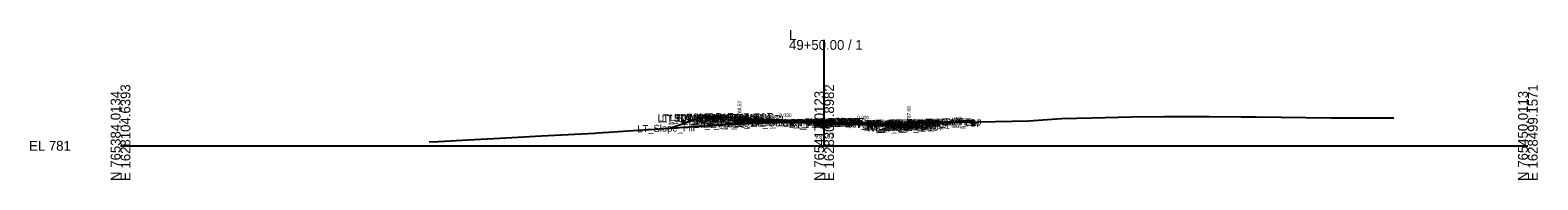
# Model space of a CAD drawing. Extents: x -26 to 4403, y -510 to 9556.
# Drawn here: x 2974.3 to 3402.8, y 9490.3 to 9532.9 of the extents above; entities that cross this region are included whole.
import ezdxf

# ---------------------------------------------------------------- set-up
doc = ezdxf.new("R2010")
doc.units = 0
for name, color, linetype in [('Default', 7, 'Continuous'), ('Exist CMT Pavement', 7, 'Continuous'), ('Exist Cross Section Cell', 7, 'Continuous'), ('Exist XS Center Line Elevation Label', 7, 'Continuous'), ('Exist XS Ground Line', 7, 'Continuous'), ('Prop CMT Conc Surface', 7, 'Continuous'), ('Prop CMT Concrete Structures', 7, 'Continuous'), ('Prop CMT Pvmt Course 1', 7, 'Continuous'), ('Prop CMT Pvmt Course 1 CG', 7, 'Continuous'), ('Prop CMT Pvmt Course 1 Wedge', 7, 'Continuous'), ('Prop CMT Pvmt Course 2', 7, 'Continuous'), ('Prop CMT Pvmt Course 2 Wedge', 7, 'Continuous'), ('Prop CMT Pvmt Course 3', 7, 'Continuous'), ('Prop CMT Pvmt Course 3 Wedge', 7, 'Continuous'), ('Prop CMT Pvmt Surface', 7, 'Continuous'), ('Prop CMT Pvmt Wedge Surface 1', 7, 'Continuous'), ('Prop CMT Pvmt Wedge Surface 2', 7, 'Continuous'), ('Prop CMT Pvmt Wedge Surface 3', 7, 'Continuous'), ('Prop CMT Slope Grass', 7, 'Continuous'), ('Prop CMT Subgrade Earthwork', 7, 'Continuous'), ('Prop XS Finish Grade CurbGutter', 7, 'Continuous'), ('Prop XS Hydro Elevations', 7, 'Continuous'), ('Prop XS SE Text', 7, 'Continuous'), ('Prop XS Side Slope Text', 7, 'Continuous'), ('Scratch_Level_0', 7, 'Continuous')]:
    doc.layers.add(name, color=color, linetype=linetype)

msp = doc.modelspace()

# ---------------------------------------------------------------- linework, layer by layer
at = {"layer": 'Exist CMT Pavement'}
for points in [[(3200, 9506.67), (3195.02, 9506.71), (3191.63, 9506.72), (3182.69, 9506.5), (3178.93, 9506.41), (3177.93, 9506.36)], [(3200, 9506.67), (3203.86, 9506.64), (3206.93, 9506.54), (3215.98, 9506.21), (3217.93, 9506.15), (3218.38, 9506.15), (3219.81, 9506.21), (3221.76, 9506.3), (3222.06, 9506.3)]]:
    msp.add_lwpolyline(points, dxfattribs=at)
at = {"layer": 'Exist Cross Section Cell'}
for p, q in [((3200, 9500), (3200, 9530.1)), ((3000, 9500), (3200, 9500)), ((3200, 9500), (3400, 9500))]:
    msp.add_line(p, q, dxfattribs=at)
at = {"layer": 'Exist XS Ground Line'}
msp.add_lwpolyline([(3087.7, 9501.12), (3090.33, 9501.26), (3098.82, 9501.68), (3107.8, 9502.14), (3119.66, 9502.81), (3132.87, 9503.52), (3134.73, 9503.62), (3135.48, 9503.64), (3138.81, 9503.86), (3149.78, 9504.63), (3150.39, 9504.64), (3174.49, 9506.2), (3175.85, 9506.27), (3176.16, 9506.28), (3178.93, 9506.41), (3182.69, 9506.5), (3191.63, 9506.72), (3195.02, 9506.71), (3200, 9506.67), (3203.86, 9506.64), (3206.93, 9506.54), (3215.98, 9506.21), (3217.93, 9506.15), (3218.38, 9506.15), (3219.81, 9506.21), (3221.76, 9506.3), (3223.51, 9506.31), (3224.89, 9506.42), (3225.44, 9506.5), (3229.86, 9506.59), (3234.45, 9506.64), (3258.2, 9507.08), (3267.44, 9507.81), (3276.18, 9507.97), (3287.38, 9508.26), (3296.52, 9508.36), (3309.39, 9508.3), (3318.51, 9508.28), (3321.3, 9508.26), (3322.77, 9508.23), (3344.04, 9507.99), (3361.94, 9507.97)], dxfattribs=at)
at = {"layer": 'Prop CMT Conc Surface'}
for points in [[(3171.42, 9508.11), (3166.42, 9508.21)], [(3175.92, 9507.52), (3175.92, 9508.02), (3175.42, 9508.02)], [(3177.93, 9507.54), (3175.92, 9507.52)], [(3222.08, 9506.22), (3224.08, 9506.08)], [(3224.08, 9506.08), (3224.08, 9506.58), (3224.58, 9506.58)], [(3228.58, 9506.67), (3233.58, 9506.77)]]:
    msp.add_lwpolyline(points, dxfattribs=at)
at = {"layer": 'Prop CMT Concrete Structures'}
for points in [[(3166.42, 9507.88), (3166.42, 9508.21)], [(3166.42, 9508.21), (3171.42, 9508.11)], [(3171.42, 9507.78), (3166.42, 9507.88)], [(3171.42, 9508.11), (3171.42, 9507.78)], [(3177.93, 9507.54), (3175.92, 9507.52), (3175.92, 9508.02), (3175.42, 9508.02)], [(3175.42, 9508.02), (3175.43, 9507.04), (3177.93, 9506.96)], [(3177.93, 9506.96), (3177.93, 9507.54)], [(3222.08, 9506.22), (3224.08, 9506.08), (3224.08, 9506.58), (3224.58, 9506.58)], [(3224.58, 9506.58), (3224.58, 9505.56), (3222.08, 9505.64)], [(3222.08, 9505.64), (3222.08, 9506.22)], [(3233.58, 9506.77), (3228.58, 9506.67)], [(3228.58, 9506.67), (3228.58, 9506.34)], [(3228.58, 9506.34), (3233.58, 9506.44)], [(3233.58, 9506.44), (3233.58, 9506.77)]]:
    msp.add_lwpolyline(points, dxfattribs=at)
at = {"layer": 'Prop CMT Pvmt Course 1'}
for points in [[(3200, 9506.88), (3177.93, 9507.54)], [(3177.93, 9507.54), (3177.93, 9507.29), (3177.93, 9507.29), (3177.93, 9507.42)], [(3177.93, 9507.42), (3200, 9506.76)], [(3200, 9506.88), (3222.08, 9506.22)], [(3200, 9506.63), (3200, 9506.88)], [(3200, 9506.63), (3200, 9506.88)], [(3222.08, 9506.09), (3200, 9506.76)], [(3200, 9506.76), (3200, 9506.63), (3200, 9506.63)], [(3200, 9506.76), (3200, 9506.63), (3200, 9506.63)], [(3222.08, 9506.22), (3222.08, 9505.97), (3222.08, 9505.97), (3222.08, 9506.09)]]:
    msp.add_lwpolyline(points, dxfattribs=at)
at = {"layer": 'Prop CMT Pvmt Course 1 CG'}
for points in [[(3177.93, 9506.96), (3174.93, 9507.05), (3174.6, 9506.73)], [(3174.6, 9506.73), (3177.93, 9506.63)], [(3177.93, 9506.63), (3177.93, 9506.96)], [(3222.08, 9505.64), (3225.08, 9505.55), (3225.42, 9505.2)], [(3222.08, 9505.3), (3222.08, 9505.64)], [(3225.42, 9505.2), (3222.08, 9505.3)]]:
    msp.add_lwpolyline(points, dxfattribs=at)
at = {"layer": 'Prop CMT Pvmt Course 1 Wedge'}
for points in [[(3177.93, 9507.42), (3178.93, 9507.39), (3182.69, 9507.28), (3191.63, 9507.01), (3195.02, 9506.91), (3200, 9506.76)], [(3177.93, 9507.29), (3177.93, 9507.42)], [(3200, 9506.67), (3198.3, 9506.68), (3195.02, 9506.78), (3191.63, 9506.88), (3182.69, 9507.15), (3178.93, 9507.26), (3177.93, 9507.29)], [(3200, 9506.76), (3200, 9506.67)], [(3200, 9506.76), (3203.8, 9506.64)], [(3200, 9506.67), (3200, 9506.76)], [(3203.8, 9506.64), (3200, 9506.67)], [(3219.18, 9506.18), (3218.38, 9506.15), (3217.93, 9506.15), (3215.98, 9506.21), (3206.93, 9506.54), (3204.23, 9506.63)], [(3204.23, 9506.63), (3206.93, 9506.55)], [(3206.93, 9506.55), (3215.98, 9506.28), (3217.93, 9506.22), (3218.38, 9506.2), (3219.18, 9506.18)]]:
    msp.add_lwpolyline(points, dxfattribs=at)
at = {"layer": 'Prop CMT Pvmt Course 2'}
for points in [[(3177.93, 9506.96), (3177.93, 9506.96), (3177.93, 9507.29), (3177.93, 9507.29)], [(3177.93, 9507.29), (3177.93, 9506.96)], [(3222.08, 9505.64), (3222.08, 9505.64), (3222.08, 9505.97), (3222.08, 9505.97)], [(3222.08, 9505.97), (3222.08, 9505.64)]]:
    msp.add_lwpolyline(points, dxfattribs=at)
at = {"layer": 'Prop CMT Pvmt Course 2 Wedge'}
for points in [[(3177.93, 9507.29), (3178.93, 9507.26), (3182.69, 9507.15), (3191.63, 9506.88), (3195.02, 9506.78), (3198.3, 9506.68)], [(3177.93, 9506.96), (3177.93, 9507.29)], [(3198.3, 9506.68), (3195.02, 9506.71), (3191.63, 9506.72), (3188.43, 9506.65), (3182.69, 9506.82), (3178.93, 9506.93), (3177.93, 9506.96)]]:
    msp.add_lwpolyline(points, dxfattribs=at)
at = {"layer": 'Prop CMT Pvmt Course 3'}
for points in [[(3177.93, 9506.96), (3177.93, 9506.96), (3177.93, 9506.63), (3177.93, 9506.63)], [(3177.93, 9506.63), (3177.93, 9506.96)], [(3222.08, 9505.64), (3222.08, 9505.64), (3222.08, 9505.3), (3222.08, 9505.3)], [(3222.08, 9505.3), (3222.08, 9505.64)]]:
    msp.add_lwpolyline(points, dxfattribs=at)
at = {"layer": 'Prop CMT Pvmt Course 3 Wedge'}
for points in [[(3177.93, 9506.96), (3178.93, 9506.93), (3182.69, 9506.82), (3188.42, 9506.65)], [(3177.93, 9506.36), (3177.93, 9506.96)], [(3188.42, 9506.65), (3182.69, 9506.5), (3178.93, 9506.41), (3177.93, 9506.36)]]:
    msp.add_lwpolyline(points, dxfattribs=at)
at = {"layer": 'Prop CMT Pvmt Surface'}
for points in [[(3200, 9506.88), (3177.93, 9507.54)], [(3200, 9506.88), (3222.08, 9506.22)]]:
    msp.add_lwpolyline(points, dxfattribs=at)
at = {"layer": 'Prop CMT Pvmt Wedge Surface 1'}
for points in [[(3177.93, 9507.29), (3177.93, 9507.54)], [(3200, 9506.76), (3177.93, 9507.42)], [(3177.93, 9507.42), (3177.93, 9507.29), (3177.93, 9507.29)], [(3200, 9506.76), (3222.08, 9506.09)], [(3222.08, 9505.97), (3222.08, 9506.22)], [(3222.08, 9506.09), (3222.08, 9505.97), (3222.08, 9505.97)]]:
    msp.add_lwpolyline(points, dxfattribs=at)
at = {"layer": 'Prop CMT Pvmt Wedge Surface 2'}
for points in [[(3177.93, 9507.29), (3177.93, 9507.54)], [(3200, 9506.63), (3177.93, 9507.29)], [(3200, 9506.63), (3222.08, 9505.97)], [(3222.08, 9505.97), (3222.08, 9506.22)]]:
    msp.add_lwpolyline(points, dxfattribs=at)
at = {"layer": 'Prop CMT Pvmt Wedge Surface 3'}
for points in [[(3177.93, 9506.96), (3177.93, 9507.54)], [(3200, 9506.3), (3177.93, 9506.96)], [(3200, 9506.3), (3222.08, 9505.64)], [(3222.08, 9505.64), (3222.08, 9506.22)]]:
    msp.add_lwpolyline(points, dxfattribs=at)
at = {"layer": 'Prop CMT Slope Grass'}
for p, q in [((3224.58, 9506.58), (3234.08, 9506.77)), ((3234.08, 9506.77), (3241.91, 9507.29))]:
    msp.add_line(p, q, dxfattribs=at)
for points in [[(3175.42, 9508.02), (3165.91, 9508.21), (3156.36, 9505.03)], [(3241.91, 9507.29), (3241.92, 9505.79), (3242.58, 9505.79), (3242.58, 9506.79)]]:
    msp.add_lwpolyline(points, dxfattribs=at)
at = {"layer": 'Prop CMT Subgrade Earthwork'}
for points in [[(3177.93, 9506.63), (3174.6, 9506.73), (3173.26, 9508.07)], [(3177.93, 9506.63), (3177.93, 9506.63)], [(3177.93, 9506.63), (3177.94, 9506.36)], [(3222.08, 9505.3), (3222.06, 9506.3)], [(3222.08, 9505.3), (3225.42, 9505.2), (3226.84, 9506.62)], [(3222.08, 9505.3), (3222.08, 9505.3)]]:
    msp.add_lwpolyline(points, dxfattribs=at)
at = {"layer": 'Prop XS Finish Grade CurbGutter'}
for p, q in [((3241.92, 9507.29), (3242.11, 9507.29)), ((3241.92, 9507.29), (3242.58, 9507.29)), ((3241.92, 9507.29), (3241.92, 9506.29)), ((3241.92, 9506.3), (3241.92, 9505.79)), ((3241.92, 9506.29), (3242.58, 9506.29)), ((3241.92, 9505.79), (3242.58, 9505.79)), ((3242.58, 9506.88), (3242.23, 9507.24)), ((3242.58, 9506.88), (3242.58, 9506.29)), ((3242.58, 9506.79), (3242.58, 9506.79)), ((3242.58, 9506.3), (3242.58, 9505.79))]:
    msp.add_line(p, q, dxfattribs=at)
msp.add_arc((3242.11, 9507.13), 0.166, 43.9997, 90, dxfattribs=at)

# ---------------------------------------------------------------- texts
at = {"layer": 'Default'}
msp.add_text('-', height=0.0001, dxfattribs=at).set_placement((3000, 9500))
at = {"layer": 'Exist Cross Section Cell'}
for s, p in [('L', (3190, 9530.1)), ('49+50.00 / 1', (3190, 9527.3)), ('EL 781', (2974, 9498.6))]:
    msp.add_text(s, height=2.8, dxfattribs=at).set_placement(p)
for s, p in [('N 765384.0134', (3000, 9490)), ('E 1628104.6393', (3002.8, 9490)), ('N 765417.0123', (3200, 9490)), ('E 1628301.8982', (3202.8, 9490)), ('N 765450.0113', (3400, 9490)), ('E 1628499.1571', (3402.8, 9490))]:
    msp.add_text(s, height=2.8, rotation=90, dxfattribs=at).set_placement(p)
at = {"layer": 'Exist XS Center Line Elevation Label'}
msp.add_text('787.67', height=1.2, dxfattribs=at).set_placement((3197.57, 9502.07))
at = {"layer": 'Prop XS Hydro Elevations'}
for s, p in [('788.52', (3176.42, 9508.52)), ('787.08', (3224.58, 9507.08))]:
    msp.add_text(s, height=1, rotation=90, dxfattribs=at).set_placement(p)
at = {"layer": 'Prop XS SE Text'}
for rotation, p in [(358.2797, (3187.24, 9508.26)), (358.2825, (3209.32, 9507.6))]:
    msp.add_text('0.030', height=1, rotation=rotation, dxfattribs=at).set_placement(p)
at = {"layer": 'Prop XS Side Slope Text'}
for s, rotation, p in [('3:1', 18.4367, (3160.15, 9507.08)), ('VAR.', 3.8202, (3236.32, 9507.09))]:
    msp.add_text(s, height=1, rotation=rotation, dxfattribs=at).set_placement(p)
at = {"layer": 'Scratch_Level_0'}
for s, p in [('LT_SDWK_Out_Top', (3152.68, 9506.94)), ('LT_Sub_Trench_Out_DLT', (3153.85, 9506.68)), ('LT_CSLP_Pnt', (3156.11, 9507.02)), ('LT_SDWK_In_Top', (3159.3, 9506.87)), ('LT_CG_Top_BOC', (3163.73, 9506.79)), ('49+50.00', (3167.57, 9506.91)), ('LT_Slope_Fill', (3146.9, 9503.84)), ('LT_SDWK_Out_Bot', (3152.71, 9506.61)), ('LT_SDWK_In_Bot', (3159.33, 9506.54)), ('LT_CG1_Shelf_Out', (3161.5, 9505.78)), ('LT_PV_Sub_Tie_Out', (3162.91, 9505.06)), ('LT_CG_Top_Face', (3163.21, 9506.77)), ('LT_CG_Bot_BOC', (3163.76, 9505.8)), ('LT_CG_Top_Gut', (3164.18, 9506.29)), ('LT_Sub_OEOP', (3164.73, 9505.53)), ('LT_PV_OEEOP_EG', (3165.49, 9505.11)), ('LT_Sub_OEEOP', (3167.16, 9505.41)), ('LT_PV2_OEEOP', (3167.25, 9506.08)), ('LT_PV3_OEEOP', (3167.25, 9505.75)), ('LT_PV1_OEEOP', (3167.82, 9506.22)), ('LT_CG_Bot_IE', (3167.86, 9505.76)), ('LT_Sub_OEOT', (3168.03, 9505.43)), ('LT_PV2_OEOT', (3168.12, 9506.1)), ('LT_PV3_OEOT', (3168.12, 9505.76)), ('LT_PV1_OEOT', (3168.69, 9506.36)), ('49+50.00', (3169.09, 9506.89)), ('49+50.00', (3169.19, 9506.59)), ('RT_PV_IEEOP_EG', (3188.16, 9505.43)), ('LT_PV_IEEOP_EG', (3188.21, 9505.43)), ('RT_PV2_IEEOP', (3189.93, 9505.43)), ('RT_PV3_IEEOP', (3189.93, 9505.1)), ('LT_PV2_IEEOP', (3189.97, 9505.43)), ('LT_PV3_IEEOP', (3189.97, 9505.1)), ('RT_PV1_IEEOP', (3190.49, 9505.57)), ('LT_PV1_IEEOP', (3190.54, 9505.57)), ('PV2_PGL', (3193.93, 9505.51)), ('PV1_PGL', (3194.49, 9505.77)), ('RT_PV_Sub_Tie_Out', (3206.98, 9505)), ('RT_Sub_Trench_Out_DLT', (3207.39, 9505.23)), ('RT_PV_OEEOP_EG', (3209.6, 9505.05)), ('RT_Sub_OEEOP', (3211.26, 9504.09)), ('RT_CG_Top_Face', (3211.31, 9505.32)), ('RT_PV2_OEEOP', (3211.36, 9504.75)), ('RT_PV3_OEEOP', (3211.36, 9504.42)), ('RT_CG1_Shelf_Out', (3211.6, 9504.28)), ('RT_PV1_OEEOP', (3211.93, 9504.89)), ('RT_CG_Bot_IE', (3211.97, 9504.43)), ('RT_Sub_OEOT', (3212.13, 9504.1)), ('RT_PV2_OEOT', (3212.23, 9504.77)), ('RT_PV3_OEOT', (3212.23, 9504.44)), ('RT_CG_Top_Gut', (3212.29, 9504.84)), ('RT_PV1_OEOT', (3212.79, 9505.03)), ('RT_CG_Top_BOC', (3212.84, 9505.34)), ('RT_CG_Bot_BOC', (3212.87, 9504.33)), ('49+50.00', (3214.48, 9505.19)), ('RT_Sub_OEOP', (3215.51, 9504)), ('RT_SDWK_In_Top', (3216.42, 9505.43)), ('RT_SDWK_In_Bot', (3216.45, 9505.09)), ('49+50.00', (3217.34, 9505.31)), ('49+50.00', (3217.39, 9505.44)), ('49+50.00', (3219.36, 9505.47)), ('RT_SDWK_Out_Top', (3219.79, 9505.49)), ('RT_SDWK_Out_Bot', (3219.83, 9505.16)), ('RT_CSLP_Pnt', (3224.24, 9505.57)), ('RT_Slope_Fill', (3224.96, 9505.45)), ('49+50.00', (3226.99, 9505.63))]:
    msp.add_text(s, height=2, rotation=1.1458, dxfattribs=at).set_placement(p)

doc.saveas('drawing.dxf')
